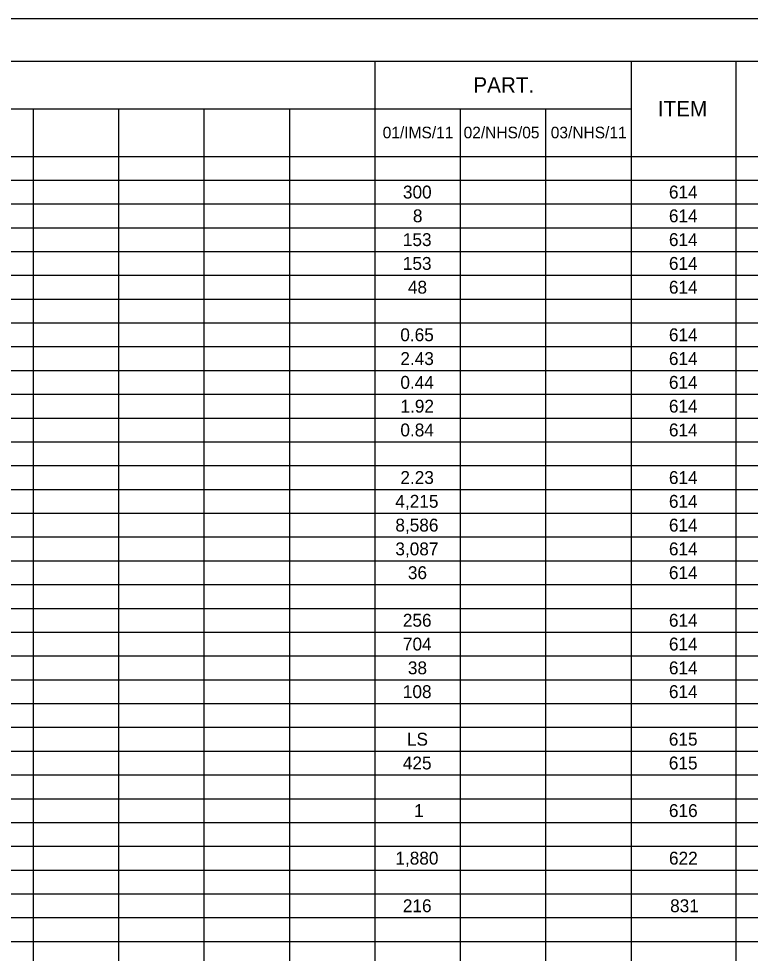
# Model space of a CAD drawing. Extents: x 0 to 34, y 0 to 22.
# Drawn here: x 8.36 to 16.97, y 11 to 22 of the extents above; entities that cross this region are included whole.
import ezdxf

# ---------------------------------------------------------------- set-up
doc = ezdxf.new("R2010")
doc.units = 0
for name, color, linetype in [('SH_Border', 7, 'Continuous'), ('SH_Cut_Line', 7, 'Continuous'), ('SH_Text', 7, 'Continuous')]:
    doc.layers.add(name, color=color, linetype=linetype)

msp = doc.modelspace()

# ---------------------------------------------------------------- linework, layer by layer
at = {"layer": 'SH_Border'}
msp.add_lwpolyline([(1.5, 21.5), (33.5, 21.5), (33.5, 0.5), (1.5, 0.5)], close=True, dxfattribs=at)
at = {"layer": 'SH_Cut_Line'}
msp.add_lwpolyline([(0, 0), (34, 0), (34, 22), (0, 22)], close=True, dxfattribs=at)
at = {"layer": 'SH_Text'}
for p, q in [((1.5, 21.5), (32.004, 21.5)), ((12.552, 21.5), (12.552, 0.5)), ((15.566, 21.5), (15.566, 0.5)), ((16.801, 21.5), (16.801, 0.5)), ((1.5, 20.94), (15.566, 20.94)), ((8.533, 20.94), (8.533, 0.5)), ((9.538, 20.94), (9.538, 0.5)), ((10.542, 20.94), (10.542, 0.5)), ((11.547, 20.94), (11.547, 0.5)), ((13.556, 20.94), (13.556, 0.5)), ((14.561, 20.94), (14.561, 0.5)), ((1.5, 20.38), (32.004, 20.38)), ((1.5, 20.1), (32.004, 20.1)), ((1.5, 19.82), (32.004, 19.82)), ((1.5, 19.54), (32.004, 19.54)), ((1.5, 19.26), (32.004, 19.26)), ((1.5, 18.98), (32.004, 18.98)), ((1.5, 18.7), (32.004, 18.7)), ((1.5, 18.42), (32.004, 18.42)), ((1.5, 18.14), (32.004, 18.14)), ((1.5, 17.86), (32.004, 17.86)), ((1.5, 17.58), (32.004, 17.58)), ((1.5, 17.3), (32.004, 17.3)), ((1.5, 17.02), (32.004, 17.02)), ((1.5, 16.74), (32.004, 16.74)), ((1.5, 16.46), (32.004, 16.46)), ((1.5, 16.18), (32.004, 16.18)), ((1.5, 15.9), (32.004, 15.9)), ((1.5, 15.62), (32.004, 15.62)), ((1.5, 15.34), (32.004, 15.34)), ((1.5, 15.06), (32.004, 15.06)), ((1.5, 14.78), (32.004, 14.78)), ((1.5, 14.5), (32.004, 14.5)), ((1.5, 14.22), (32.004, 14.22)), ((1.5, 13.94), (32.004, 13.94)), ((1.5, 13.66), (32.004, 13.66)), ((1.5, 13.38), (32.004, 13.38)), ((1.5, 13.1), (32.004, 13.1)), ((1.5, 12.82), (32.004, 12.82)), ((1.5, 12.54), (32.004, 12.54)), ((1.5, 12.26), (32.004, 12.26)), ((1.5, 11.98), (32.004, 11.98)), ((1.5, 11.7), (32.004, 11.7)), ((1.5, 11.42), (32.004, 11.42)), ((1.5, 11.14), (32.004, 11.14))]:
    msp.add_line(p, q, dxfattribs=at)

# ---------------------------------------------------------------- texts
for s, height, p in [('PART.', 0.1818, (13.711, 21.129)), ('ITEM', 0.1818, (15.882, 20.849)), ('01/IMS/11', 0.1364, (12.645, 20.592)), ('02/NHS/05', 0.1364, (13.597, 20.592)), ('03/NHS/11', 0.1364, (14.622, 20.592)), ('300', 0.1515, (12.883, 19.884)), ('614', 0.1515, (16.012, 19.884)), ('8', 0.152, (13, 19.604)), ('614', 0.1515, (16.012, 19.604)), ('153', 0.1515, (12.882, 19.324)), ('614', 0.1515, (16.012, 19.324)), ('153', 0.1515, (12.882, 19.044)), ('614', 0.1515, (16.012, 19.044)), ('48', 0.1515, (12.941, 18.764)), ('614', 0.1515, (16.012, 18.764)), ('0.65', 0.1515, (12.852, 18.204)), ('614', 0.1515, (16.012, 18.204)), ('2.43', 0.1515, (12.853, 17.924)), ('614', 0.1515, (16.012, 17.924)), ('0.44', 0.1515, (12.853, 17.644)), ('614', 0.1515, (16.012, 17.644)), ('1.92', 0.1515, (12.854, 17.364)), ('614', 0.1515, (16.012, 17.364)), ('0.84', 0.1515, (12.853, 17.084)), ('614', 0.1515, (16.012, 17.084)), ('2.23', 0.1515, (12.853, 16.524)), ('614', 0.1515, (16.012, 16.524)), ('4,215', 0.1515, (12.794, 16.244)), ('614', 0.1515, (16.012, 16.244)), ('8,586', 0.1515, (12.794, 15.964)), ('614', 0.1515, (16.012, 15.964)), ('3,087', 0.1515, (12.794, 15.684)), ('614', 0.1515, (16.012, 15.684)), ('36', 0.1515, (12.941, 15.404)), ('614', 0.1515, (16.012, 15.404)), ('256', 0.1515, (12.882, 14.844)), ('614', 0.1515, (16.012, 14.844)), ('704', 0.1515, (12.883, 14.564)), ('614', 0.1515, (16.012, 14.564)), ('38', 0.1515, (12.941, 14.284)), ('614', 0.1515, (16.012, 14.284)), ('108', 0.1515, (12.882, 14.004)), ('614', 0.1515, (16.012, 14.004)), ('LS', 0.1515, (12.93, 13.444)), ('615', 0.1515, (16.011, 13.444)), ('425', 0.1515, (12.882, 13.164)), ('615', 0.1515, (16.011, 13.164)), ('1', 0.152, (13.015, 12.604)), ('616', 0.1515, (16.012, 12.604)), ('1,880', 0.1515, (12.794, 12.044)), ('622', 0.1515, (16.013, 12.044)), ('216', 0.1515, (12.882, 11.484)), ('831', 0.1515, (16.026, 11.484))]:
    msp.add_text(s, height=height, dxfattribs=at).set_placement(p)

doc.saveas('drawing.dxf')
